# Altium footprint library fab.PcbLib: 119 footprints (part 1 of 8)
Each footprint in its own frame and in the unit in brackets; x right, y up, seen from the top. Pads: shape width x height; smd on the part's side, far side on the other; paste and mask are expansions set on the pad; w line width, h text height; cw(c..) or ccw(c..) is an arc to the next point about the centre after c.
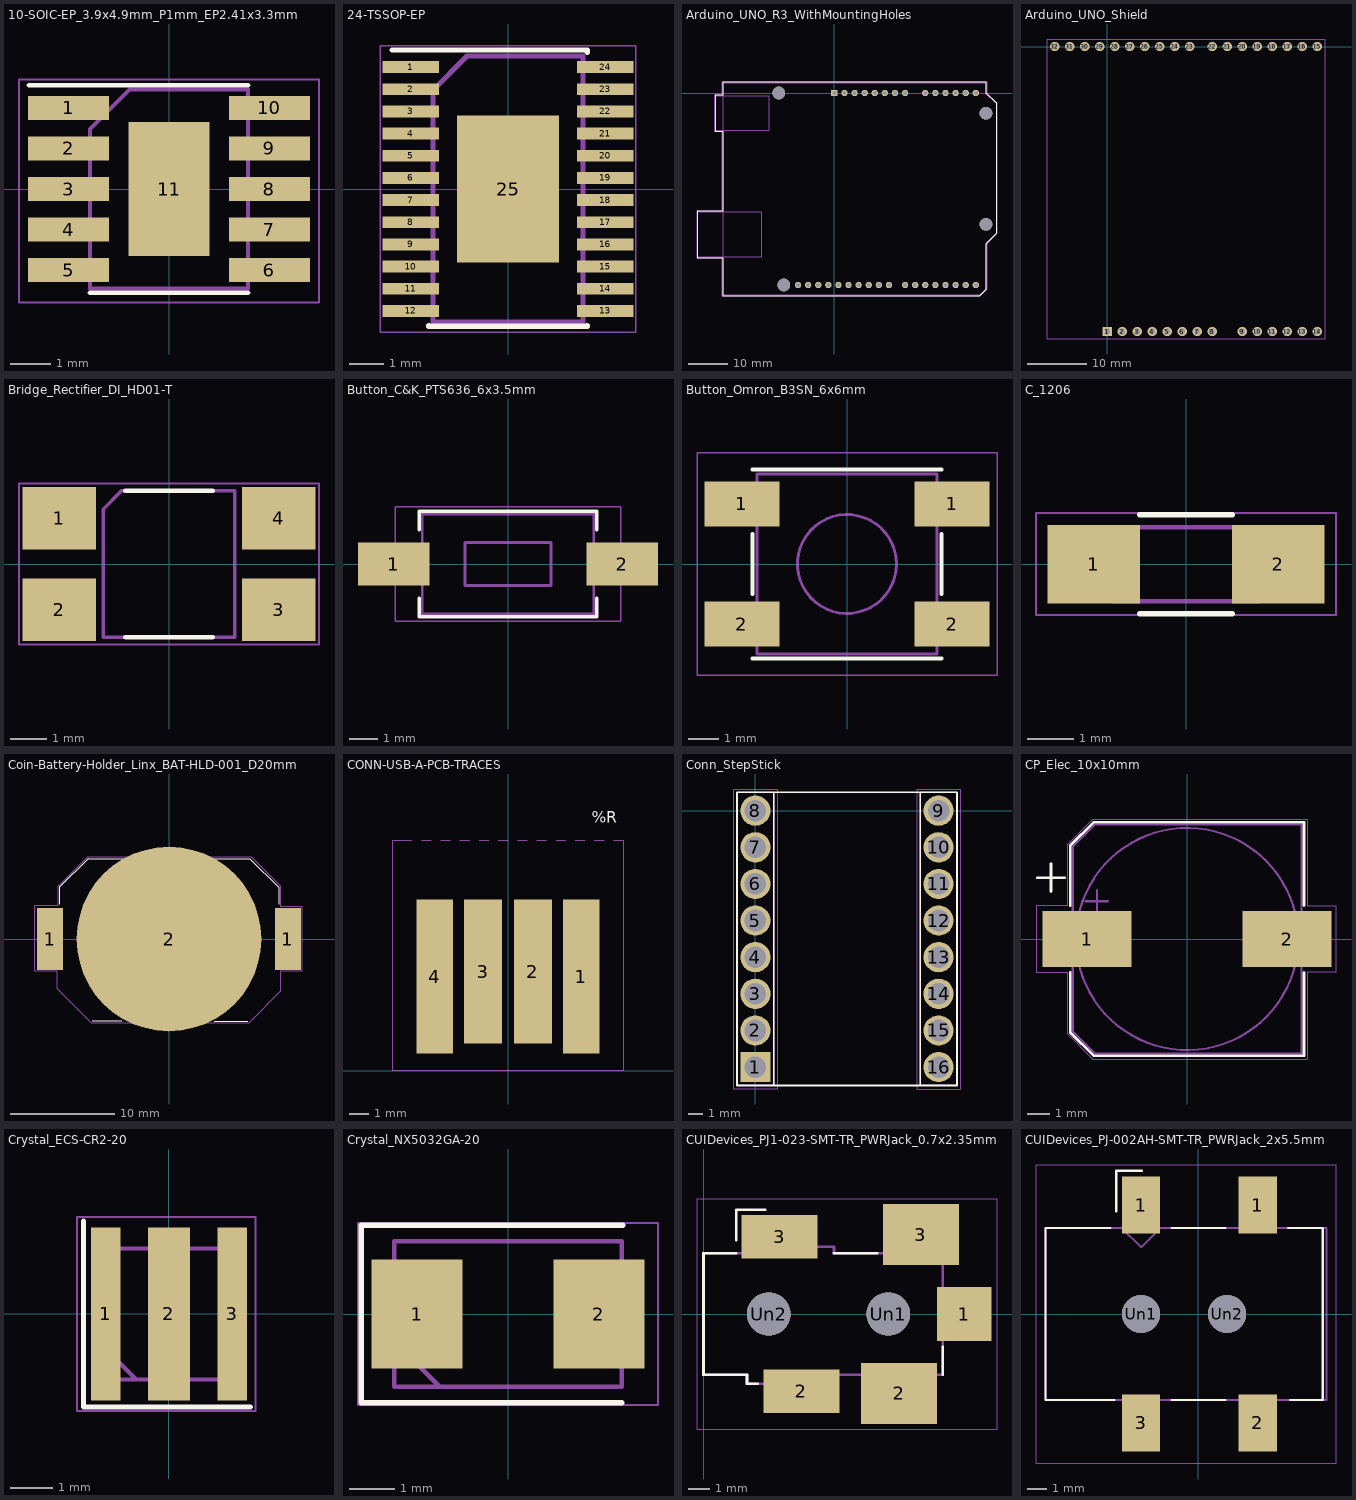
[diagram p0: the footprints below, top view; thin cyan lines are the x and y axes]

## 10-SOIC-EP_3.9x4.9mm_P1mm_EP2.41x3.3mm [mm]
pads (11):
  rect 2x0.6 smd: 1(-2.475,2) 2(-2.475,1) 3(-2.475,0) 4(-2.475,-1) 5(-2.475,-2) 6(2.475,-2) 7(2.475,-1) 8(2.475,0) 9(2.475,1) 10(2.475,2)
  rect 2x3.3 smd: 11(0,0)
F.SilkS:
  lines w0.12: -3.45,2.56 0,2.56 1.95,2.56 ; -1.95,-2.56 0,-2.56 1.95,-2.56
B.CrtYd:
  lines w0.05: -3.7,-2.8 3.7,-2.8 3.7,2.7 -3.7,2.7 -3.7,-2.8
F.Fab:
  lines w0.1: -1.95,-2.45 1.95,-2.45 1.95,2.45 -0.975,2.45 -1.95,1.475 -1.95,-2.45

## 24-TSSOP-EP [mm]
pads (25):
  rect 1.65x0.35 smd: 1(-2.85,3.575) 2(-2.85,2.925) 3(-2.85,2.275) 4(-2.85,1.625) 5(-2.85,0.975) 6(-2.85,0.325) 7(-2.85,-0.325) 8(-2.85,-0.975) 9(-2.85,-1.625) 10(-2.85,-2.275) 11(-2.85,-2.925) 12(-2.85,-3.575) 13(2.85,-3.575) 14(2.85,-2.925) 15(2.85,-2.275) 16(2.85,-1.625) 17(2.85,-0.975) 18(2.85,-0.325) 19(2.85,0.325) 20(2.85,0.975) 21(2.85,1.625) 22(2.85,2.275) 23(2.85,2.925) 24(2.85,3.575)
  rect 3x4.32 smd: 25(0,0)
F.SilkS:
  lines w0.15: -3.4,4.075 2.325,4.075 ; -2.325,-4 -2.325,-4.025 2.325,-4.025 2.325,-4 ; 2.325,4 2.325,4.025
F.CrtYd:
  lines w0.05: -3.75,-4.2 -3.75,4.2 3.75,4.2 3.75,-4.2 -3.75,-4.2
F.Fab:
  lines w0.15: -2.2,-3.9 2.2,-3.9 2.2,3.9 -1.2,3.9 -2.2,2.9 -2.2,-3.9
  text "%R" at -0.313,-0.234 h0.8

## Arduino_UNO_R3_WithMountingHoles [mm]
pads (36):
  rect 1.6x1.6 hole 1: 1(0,0)
  rrect100% 1.6x1.6 hole 1: 2(2.54,0) 3(5.08,0) 4(7.62,0) 5(10.16,0) 6(12.7,0) 7(15.24,0) 8(17.78,0) 9(22.86,0) 10(25.4,0) 11(27.94,0) 12(30.48,0) 13(33.02,0) 14(35.56,0) 15(35.56,-48.26) 16(33.02,-48.26) 17(30.48,-48.26) 18(27.94,-48.26) 19(25.4,-48.26) 20(22.86,-48.26) 21(20.32,-48.26) 22(17.78,-48.26) 23(13.72,-48.26) 24(11.18,-48.26) 25(8.64,-48.26) 26(6.1,-48.26) 27(3.56,-48.26) 28(1.02,-48.26) 29(-1.52,-48.26) 30(-4.06,-48.26) 31(-6.6,-48.26) 32(-9.14,-48.26)
  round 3.2 hole 3.2: Un1(-13.97,0) Un2(-12.7,-48.26) Un3(38.1,-33.02) Un4(38.1,-5.08)
F.SilkS:
  lines w0.12: -34.42,-41.4 -28.07,-41.4 -28.07,-50.93 36.58,-50.93 38.23,-49.28 38.23,-37.85 40.77,-35.31 40.77,-2.54 38.23,0 38.23,2.67 -28.07,2.67 -28.07,-0.51 -29.97,-0.51 -29.97,-9.65 -28.07,-9.65 -28.07,-29.72 -34.42,-29.72 -34.42,-41.4
F.CrtYd:
  lines w0.05: -34.54,-41.53 -34.54,-29.59 -28.19,-29.59 -28.19,-9.78 -30.1,-9.78 -30.1,-0.38 -28.19,-0.38 -28.19,2.79 38.35,2.79 38.35,0 40.89,-2.54 40.89,-35.31 38.35,-37.85 38.35,-49.28 36.58,-51.05 -28.19,-51.05 -28.19,-41.53 -34.54,-41.53
F.Fab:
  lines w0.1: -34.29,-41.27 -34.29,-29.84 -18.41,-29.84 -18.41,-41.27 -34.29,-41.27 ; -29.84,-9.53 -29.84,-0.64 -16.51,-0.64 -16.51,-9.53 -29.84,-9.53 ; -27.94,-50.8 -27.94,2.54 38.1,2.54 38.1,0 40.64,-2.54 40.64,-35.31 38.1,-37.85 38.1,-49.28 36.58,-50.8 -27.94,-50.8
  text "%R" at -0.393,-20.614 h1

## Arduino_UNO_Shield [mm]
pads (32):
  rect 1.6x1.6 hole 1: 1(0,-48.26)
  rrect100% 1.6x1.6 hole 1: 2(2.54,-48.26) 3(5.08,-48.26) 4(7.62,-48.26) 5(10.16,-48.26) 6(12.7,-48.26) 7(15.24,-48.26) 8(17.78,-48.26) 9(22.86,-48.26) 10(25.4,-48.26) 11(27.94,-48.26) 12(30.48,-48.26) 13(33.02,-48.26) 14(35.56,-48.26) 15(35.56,0) 16(33.02,0) 17(30.48,0) 18(27.94,0) 19(25.4,0) 20(22.86,0) 21(20.32,0) 22(17.78,0) 23(13.974,0) 24(11.434,0) 25(8.894,0) 26(6.354,0) 27(3.814,0) 28(1.274,0) 29(-1.266,0) 30(-3.806,0) 31(-6.346,0) 32(-8.886,0)
F.Fab:
  lines w0.12: -10.16,-49.53 36.83,-49.53 36.83,1.27 -10.16,1.27 -10.16,-49.53
  text "%R" at -0.393,-20.614 h1

## Bridge_Rectifier_DI_HD01-T [mm]
pads (4):
  rect 2x1.7 smd: 1(-3,1.25) 2(-3,-1.25) 3(3,-1.25) 4(3,1.25)
F.SilkS:
  lines w0.12: -1.2,-2 1.2,-2 ; -1.2,2 1.2,2
F.CrtYd:
  lines w0.05: -4.1,-2.2 4.1,-2.2 4.1,2.2 -4.1,2.2 -4.1,-2.2
F.Fab:
  lines w0.1: -1.8,-2 1.8,-2 1.8,2 -1.3,2 -1.8,1.5 -1.8,-2
  text "%R" at -0.393,-0.294 h1

## Button_C&K_PTS636_6x3.5mm [mm]
pads (2):
  rect 2.5x1.5 smd: 1(-4,0) 2(4,0)
F.SilkS:
  lines w0.12: -3.1,-1.2 -3.1,-1.85 3.1,-1.85 3.1,-1.2 ; -3.1,1.2 -3.1,1.85 3.1,1.85 3.1,1.2
F.CrtYd:
  lines w0.05: -3.95,-2 -3.95,2 3.95,2 3.95,-2 -3.95,-2
F.Fab:
  lines w0.1: -3,-1.75 -3,1.75 3,1.75 3,-1.75 -3,-1.75 ; -1.5,-0.75 -1.5,0.75 1.5,0.75 1.5,-0.75 -1.5,-0.75
  text "%R" at -0.393,2.356 h1

## Button_Omron_B3SN_6x6mm [mm]
pads (4):
  rect 2.5x1.5 smd: 1(-3.5,2) 1(3.5,2) 2(-3.5,-2) 2(3.5,-2)
F.SilkS:
  lines w0.12: -3.15,-3.15 3.15,-3.15 ; -3.15,-1 -3.15,1 ; -3.15,3.15 3.15,3.15 ; 3.15,-1 3.15,1
F.CrtYd:
  lines w0.05: -5,-3.7 -5,3.7 5,3.7 5,-3.7 -5,-3.7
F.Fab:
  circle w0.1: c0,0 r1.65
  lines w0.1: -3,-3 -3,3 3,3 3,-3 -3,-3
  text "%R" at -0.393,4.206 h1

## C_1206 [mm]
pads (2):
  rect 2x1.7 smd: 1(-2,0) 2(2,0)
F.SilkS:
  lines w0.12: -1,-1.07 1,-1.07 ; -1,1.07 1,1.07
F.CrtYd:
  lines w0.05: -3.25,-1.1 -3.25,1.11 3.25,1.11 3.25,-1.1 -3.25,-1.1
F.Fab:
  lines w0.1: -1.6,-0.8 -1.6,0.8 1.6,0.8 1.6,-0.8 -1.6,-0.8
  text "%R" at -0.275,-0.205 h0.7

## Coin-Battery-Holder_Linx_BAT-HLD-001_D20mm [mm]
pads (3):
  rect 2.5x6 smd: 1(-11.45,0) 1(11.45,0)
  round 17.8 smd: 2(0,0)
F.SilkS:
  lines w0.12: -10.55,3.35 -10.55,5 -7.8,7.75 7.8,7.75 10.55,5 10.55,3.33 ; -7.37,-7.89 -4.57,-7.89 ; 4.36,-7.96 7.58,-7.96
F.CrtYd:
  lines w0.05: -12.93,-3.13 -10.77,-3.13 -10.77,-4.79 -7.45,-8.11 7.66,-8.11 10.74,-5.02 10.74,-3.09 12.8,-3.09 12.8,3.17 10.71,3.17 10.71,5.14 7.92,7.93 -7.82,7.93 -10.68,5.07 -10.68,3.26 -12.93,3.26 -12.93,-3.13
F.Fab:
  text "%R" at -0.393,2.606 h1

## CONN-USB-A-PCB-TRACES [mm]
pads (4):
  rect 1.9x8 smd: 1(3.81,4.9) 4(-3.81,4.9)
  rect 2x7.5 smd: 2(1.3,5.15) 3(-1.3,5.15)
F.SilkS:
  text "%R" at 4.357,12.706 h1
F.Fab:
  lines w0.041: -5,12 -6,12 -6,0 6,0 6,12 5.5,12 ; -4.5,12 -4,12 ; -3.5,12 -3,12 ; -2.5,12 -2,12 ; -1.5,12 -1,12 ; -0.5,12 0,12 ; 0.5,12 1,12 ; 1.5,12 2,12 ; 2.5,12 3,12 ; 3.5,12 4,12 ; 4.5,12 5,12
  text "%R" at -0.393,5.956 h1

## Conn_StepStick [mm]
pads (16):
  rect 2.1x2.1 hole 1.5: 1(0,-17.78)
  round 2.1 hole 1.5: 2(0,-15.24) 3(0,-12.7) 4(0,-10.16) 5(0,-7.62) 6(0,-5.08) 7(0,-2.54) 8(0,0) 9(12.7,0) 10(12.7,-2.54) 11(12.7,-5.08) 12(12.7,-7.62) 13(12.7,-10.16) 14(12.7,-12.7) 15(12.7,-15.24) 16(12.7,-17.78)
F.SilkS:
  lines w0.12: 1.27,-19.05 1.27,1.27 ; 11.43,-19.05 11.43,1.27 ; -1.27,-19.05 -1.27,1.27 13.97,1.27 13.97,-19.05 -1.27,-19.05
F.CrtYd:
  lines w0.05: -1.5,-19.3 -1.5,1.5 1.5,1.5 1.5,-19.3 -1.5,-19.3 ; 11.2,-19.3 14.2,-19.3 14.2,1.5 11.2,1.5 11.2,-19.3
F.Fab:
  lines w0.1: -1.27,-19.05 -1.27,1.27 1.27,1.27 1.27,-19.05 -1.27,-19.05 ; 11.43,-19.05 11.43,1.27 13.97,1.27 13.97,-19.05 11.43,-19.05
  text "%R" at 5.957,-9.184 h1

## CP_Elec_10x10mm [mm]
pads (2):
  rect 4x2.5 smd: 1(-4.5,0) 2(4.5,0)
F.SilkS:
  lines w0.12: -6.75,2.76 -5.5,2.76 ; -6.125,2.135 -6.125,3.385 ; -5.26,-1.51 -5.26,-4.196 -4.196,-5.26 5.26,-5.26 5.26,-1.51 ; -5.26,1.51 -5.26,4.196 -4.196,5.26 5.26,5.26 5.26,1.51
F.CrtYd:
  lines w0.05: -6.8,-1.5 -6.8,1.5 -5.4,1.5 -5.4,4.25 -4.25,5.4 5.4,5.4 5.4,1.5 6.7,1.5 6.7,-1.5 5.4,-1.5 5.4,-5.4 -4.25,-5.4 -5.4,-4.25 -5.4,-1.5 -6.8,-1.5
F.Fab:
  circle w0.1: c0,0 r5
  lines w0.1: -4.558,1.7 -3.558,1.7 ; -4.058,1.2 -4.058,2.2 ; -5.15,-4.15 -5.15,4.15 -4.15,5.15 5.15,5.15 5.15,-5.15 -4.15,-5.15 -5.15,-4.15
  text "%R" at -0.393,-0.294 h1

## Crystal_ECS-CR2-20 [mm]
pads (3):
  rect 0.7x4.1 smd: 1(-1.5,0) 3(1.5,0)
  rect 1x4.1 smd: 2(0,0)
F.SilkS:
  lines w0.12: -2.025,2.2 -2.025,-2.2 1.925,-2.2
F.CrtYd:
  lines w0.05: -2.175,-2.3 2.05,-2.3 2.05,2.3 -2.175,2.3 -2.175,-2.3
F.Fab:
  lines w0.1: -1.775,-0.55 -0.775,-1.55 ; -1.775,-1.55 1.75,-1.55 1.75,1.55 -1.775,1.55 -1.775,-1.55
  text "%R" at -0.393,-0.294 h1

## Crystal_NX5032GA-20 [mm]
pads (2):
  rect 2x2.4 smd: 1(-2,0) 2(2,0)
F.SilkS:
  lines w0.12: 2.5,-1.95 -3.225,-1.95 -3.225,1.95 2.525,1.95
F.CrtYd:
  lines w0.05: -3.3,-2 -3.3,2 3.3,2 3.3,-2 -3.3,-2
F.Fab:
  lines w0.1: -2.5,-0.6 -1.5,-1.6 ; -2.5,-1.6 2.5,-1.6 2.5,1.6 -2.5,1.6 -2.5,-1.6
  text "%R" at -0.393,-0.294 h1

## CUIDevices_PJ1-023-SMT-TR_PWRJack_0.7x2.35mm [mm]
pads (7):
  rect 2.5x2.5 smd: 1(12,0)
  rect 3.5x2 smd: 2(4.5,-3.55) 3(3.5,3.55)
  rect 3.5x2.8 smd: 2(9,-3.65) 3(10,3.65)
  round 2 hole 2: Un1(8.5,0) Un2(3,0)
F.SilkS:
  lines w0.12: 1.5,2.8 0,2.8 0,-2.8 2,-2.8 2,-3.2 2.5,-3.2 ; 1.5,3.4 1.5,4.8 2.84,4.8 ; 6,2.8 8,2.8 ; 11,-2.8 11,-1.5
F.CrtYd:
  lines w0.05: -0.3,-5.3 13.5,-5.3 13.5,5.3 -0.3,5.3 -0.3,-5.3
F.Fab:
  lines w0.1: 0,-2.8 0,2.8
  lines w0.12: 0,-2.8 2,-2.8 2,-3.2 5.6,-3.2 5.6,-2.8 11,-2.8 11,2.8 6,2.8 6,3.1 2.1,3.1 2.1,2.8 0,2.8
  text "%R" at 5.607,1.206 h1

## CUIDevices_PJ-002AH-SMT-TR_PWRJack_2x5.5mm [mm]
pads (6):
  rect 2x3 smd: 1(-3,5.7) 1(3.1,5.7) 2(3.1,-5.7) 3(-3,-5.7)
  round 2 hole 2: Un1(-3,0) Un2(1.5,0)
F.SilkS:
  lines w0.12: -4.6,4.5 -8,4.5 -8,-4.5 -4.39,-4.5 ; -4.3,5.36 -4.3,7.5 -2.96,7.5 ; -1.4,-4.5 1.4,-4.5 ; -1.4,4.5 1.4,4.5 ; 4.7,4.5 6.5,4.5 6.5,-4.5 4.8,-4.5
F.CrtYd:
  lines w0.05: -8.5,-7.8 7.2,-7.8 7.2,7.8 -8.5,7.8 -8.5,-7.8
F.Fab:
  lines w0.1: -8,-4.5 -8,4.5 -4,4.5 -3,3.5 -2,4.5 6.7,4.5 6.7,-4.5 -8,-4.5
  text "%R" at -0.893,-0.794 h1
